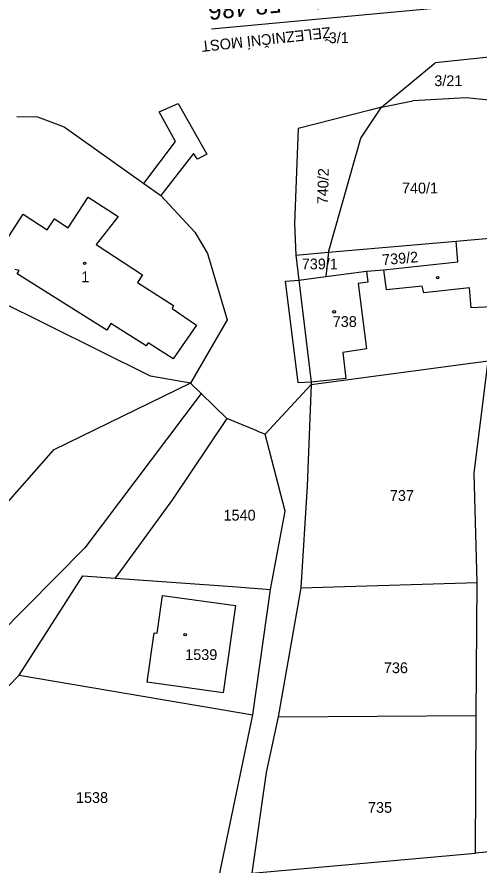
# Model space of a CAD drawing. Extents: x -563148 to -561712, y -1182311 to -1179502.
# Drawn here: x -562644.1 to -562579.8, y -1180775.6 to -1180657.6 of the extents above; entities that cross this region are included whole.
import ezdxf

# ---------------------------------------------------------------- set-up
doc = ezdxf.new("R2010")
doc.units = 0
for name, color, linetype in [('Vrstva 18', 7, 'Continuous'), ('Vrstva 55', 7, 'Continuous'), ('Vrstva 56', 7, 'Continuous'), ('Vrstva 57', 7, 'Continuous')]:
    doc.layers.add(name, color=color, linetype=linetype)

msp = doc.modelspace()

# ---------------------------------------------------------------- linework, layer by layer
at = {"layer": 'Vrstva 18'}
msp.add_line((-562573.1, -1180655.16), (-562617.05, -1180659.27), dxfattribs=at)
at = {"layer": 'Vrstva 55'}
for p, q in [((-562576.79, -1180662.97), (-562585.95, -1180663.95)), ((-562593.38, -1180670.13), (-562585.95, -1180663.95)), ((-562581.62, -1180668.81), (-562589.03, -1180669.24)), ((-562577.02, -1180669.29), (-562581.62, -1180668.81)), ((-562593.38, -1180670.13), (-562589.03, -1180669.24)), ((-562595.17, -1180670.56), (-562604.98, -1180673.1)), ((-562596.27, -1180674.44), (-562593.38, -1180670.13)), ((-562593.38, -1180670.13), (-562595.17, -1180670.56)), ((-562644.12, -1180671.43), (-562641.22, -1180671.48)), ((-562641.22, -1180671.48), (-562637.53, -1180672.83)), ((-562637.53, -1180672.83), (-562626.43, -1180680.74)), ((-562604.98, -1180673.1), (-562605.51, -1180686.33)), ((-562600.75, -1180690.32), (-562596.27, -1180674.44)), ((-562626.43, -1180680.74), (-562624.11, -1180682.4)), ((-562636.98, -1180686.93), (-562634.18, -1180682.63)), ((-562634.18, -1180682.63), (-562630.02, -1180685.33)), ((-562624.11, -1180682.4), (-562619.38, -1180687.5)), ((-562646.22, -1180689.61), (-562643.21, -1180685.01)), ((-562643.21, -1180685.01), (-562639.88, -1180687.18)), ((-562630.02, -1180685.33), (-562633.1, -1180689.25)), ((-562639.88, -1180687.18), (-562638.88, -1180685.67)), ((-562638.88, -1180685.67), (-562636.98, -1180686.93)), ((-562605.51, -1180686.33), (-562605.33, -1180690.73)), ((-562619.38, -1180687.5), (-562617.61, -1180690.49)), ((-562600.75, -1180690.32), (-562583.02, -1180688.75)), ((-562583.02, -1180688.75), (-562578.39, -1180688.37)), ((-562582.8, -1180691.64), (-562583.02, -1180688.75)), ((-562633.1, -1180689.25), (-562626.65, -1180693.45)), ((-562625.53, -1180707.56), (-562660.56, -1180690.19)), ((-562617.61, -1180690.49), (-562614.85, -1180699.7)), ((-562605.33, -1180690.73), (-562600.75, -1180690.32)), ((-562605.33, -1180690.73), (-562604.89, -1180694.18)), ((-562600.75, -1180690.32), (-562601.15, -1180693.69)), ((-562593.07, -1180692.75), (-562582.8, -1180691.64)), ((-562643.77, -1180692.84), (-562644.37, -1180692.69)), ((-562644.07, -1180693.32), (-562643.77, -1180692.84)), ((-562631.62, -1180701.17), (-562644.07, -1180693.32)), ((-562626.65, -1180693.45), (-562627.33, -1180694.5)), ((-562604.89, -1180694.18), (-562601.15, -1180693.69)), ((-562601.15, -1180693.69), (-562595.51, -1180692.96)), ((-562595.51, -1180692.96), (-562593.07, -1180692.75)), ((-562627.33, -1180694.5), (-562622.33, -1180697.74)), ((-562604.89, -1180694.18), (-562603.17, -1180708.41)), ((-562622.33, -1180697.74), (-562622.52, -1180698.12)), ((-562622.52, -1180698.12), (-562619.15, -1180700.46)), ((-562631.02, -1180700.23), (-562631.62, -1180701.17)), ((-562626.13, -1180703.35), (-562631.02, -1180700.23)), ((-562619.15, -1180700.46), (-562622.37, -1180705.16)), ((-562614.85, -1180699.7), (-562619.98, -1180708.54)), ((-562625.86, -1180702.92), (-562626.13, -1180703.35)), ((-562622.37, -1180705.16), (-562625.86, -1180702.92)), ((-562603.18, -1180708.71), (-562578.59, -1180705.44)), ((-562580.51, -1180721.07), (-562578.59, -1180705.44)), ((-562619.98, -1180708.54), (-562625.53, -1180707.56)), ((-562619.98, -1180708.54), (-562639.06, -1180717.85)), ((-562618.49, -1180709.98), (-562619.98, -1180708.54)), ((-562603.18, -1180708.71), (-562609.6, -1180715.65)), ((-562603.18, -1180708.71), (-562603.72, -1180722.85)), ((-562603.17, -1180708.41), (-562603.18, -1180708.71)), ((-562618.49, -1180709.98), (-562634.68, -1180731.46)), ((-562614.89, -1180713.45), (-562618.49, -1180709.98)), ((-562614.89, -1180713.45), (-562622.48, -1180724.74)), ((-562606.81, -1180726.34), (-562609.6, -1180715.65)), ((-562639.06, -1180717.85), (-562664.65, -1180746.97)), ((-562580.09, -1180736.3), (-562580.51, -1180721.07)), ((-562603.72, -1180722.85), (-562604.63, -1180737.02)), ((-562622.48, -1180724.74), (-562630.42, -1180735.67)), ((-562608.85, -1180737.25), (-562606.81, -1180726.34)), ((-562634.68, -1180731.46), (-562648.04, -1180744.97)), ((-562643.77, -1180749.19), (-562634.92, -1180735.34)), ((-562634.92, -1180735.34), (-562630.42, -1180735.67)), ((-562611.28, -1180754.69), (-562608.85, -1180737.25)), ((-562604.63, -1180737.02), (-562607.78, -1180755)), ((-562604.63, -1180737.02), (-562580.09, -1180736.3)), ((-562580.22, -1180754.8), (-562580.09, -1180736.3)), ((-562643.77, -1180749.19), (-562656.73, -1180762.3)), ((-562643.77, -1180749.19), (-562611.28, -1180754.69)), ((-562616.02, -1180777.4), (-562611.28, -1180754.69)), ((-562607.78, -1180755), (-562609.42, -1180762.74)), ((-562607.78, -1180755), (-562580.22, -1180754.8)), ((-562580.34, -1180773.98), (-562580.22, -1180754.8)), ((-562609.42, -1180762.74), (-562611.42, -1180776.77)), ((-562611.42, -1180776.77), (-562580.34, -1180773.98)), ((-562577.9, -1180773.76), (-562580.34, -1180773.98))]:
    msp.add_line(p, q, dxfattribs=at)
for points in [[(-562609.6, -1180715.65), (-562610.35, -1180715.34), (-562610.83, -1180715.14), (-562614.89, -1180713.45)], [(-562630.42, -1180735.67), (-562613.47, -1180736.91), (-562612.97, -1180736.95), (-562608.85, -1180737.25)]]:
    msp.add_lwpolyline(points, dxfattribs=at)
at = {"layer": 'Vrstva 56'}
for p, q in [((-562624.33, -1180670.76), (-562621.66, -1180669.62)), ((-562621.66, -1180669.62), (-562617.69, -1180676.65)), ((-562622.03, -1180674.91), (-562624.33, -1180670.76)), ((-562626.43, -1180680.74), (-562622.03, -1180674.91)), ((-562619.53, -1180676.56), (-562624.11, -1180682.4)), ((-562618.97, -1180677.34), (-562619.53, -1180676.56)), ((-562617.69, -1180676.65), (-562618.97, -1180677.34)), ((-562595.51, -1180692.96), (-562595.3, -1180694.48)), ((-562592.7, -1180695.52), (-562593.07, -1180692.75)), ((-562606.77, -1180694.33), (-562604.89, -1180694.18)), ((-562604.98, -1180708.49), (-562606.77, -1180694.33)), ((-562595.3, -1180694.48), (-562596.65, -1180694.68)), ((-562596.65, -1180694.68), (-562595.5, -1180703.75)), ((-562587.75, -1180695.04), (-562592.7, -1180695.52)), ((-562587.53, -1180695.98), (-562587.75, -1180695.04)), ((-562581.15, -1180695.28), (-562587.53, -1180695.98)), ((-562580.91, -1180698.06), (-562581.15, -1180695.28)), ((-562577.99, -1180697.93), (-562580.91, -1180698.06)), ((-562595.5, -1180703.75), (-562598.77, -1180704.25)), ((-562598.77, -1180704.25), (-562598.38, -1180707.89)), ((-562598.38, -1180707.89), (-562603.17, -1180708.41)), ((-562603.17, -1180708.41), (-562604.98, -1180708.49)), ((-562624.6, -1180743.34), (-562623.85, -1180738.09)), ((-562623.85, -1180738.09), (-562613.69, -1180739.51)), ((-562613.69, -1180739.51), (-562615.4, -1180751.63)), ((-562626.01, -1180750.15), (-562625.03, -1180743.28)), ((-562625.03, -1180743.28), (-562624.6, -1180743.34)), ((-562615.4, -1180751.63), (-562626.01, -1180750.15))]:
    msp.add_line(p, q, dxfattribs=at)
at = {"layer": 'Vrstva 57'}
for centre in [(-562634.69, -1180691.86), (-562585.59, -1180693.85), (-562599.99, -1180698.6), (-562620.71, -1180743.55)]:
    msp.add_circle(centre, 0.175, dxfattribs=at)

# ---------------------------------------------------------------- texts
at = {"layer": 'Vrstva 18'}
for s, height, rotation, p in [('km 58,486', 2.5, 186.2506, (-562602.13, -1180653.82)), ('ŽELEZNIČNÍ MOST', 1.5, 186.3054, (-562600.58, -1180658.95))]:
    msp.add_text(s, height=height, rotation=rotation, dxfattribs=at).set_placement(p)
at = {"layer": 'Vrstva 57'}
for s, p in [('3/1', (-562600.74, -1180661.2)), ('3/21', (-562586.06, -1180667.18)), ('740/1', (-562590.56, -1180682.12)), ('739/1', (-562604.49, -1180692.69)), ('1', (-562635.16, -1180694.48)), ('738', (-562600.18, -1180700.71)), ('737', (-562592.24, -1180724.93)), ('1540', (-562615.37, -1180727.67)), ('1539', (-562620.7, -1180747.08)), ('736', (-562593.07, -1180748.91)), ('1538', (-562635.89, -1180766.98)), ('735', (-562595.28, -1180768.35))]:
    msp.add_text(s, height=1.5, dxfattribs=at).set_placement(p)
for s, rotation, p in [('740/2', 88.5891, (-562600.85, -1180683.65)), ('739/2', 4.9234, (-562593.25, -1180692.12))]:
    msp.add_text(s, height=1.5, rotation=rotation, dxfattribs=at).set_placement(p)

doc.saveas('drawing.dxf')
